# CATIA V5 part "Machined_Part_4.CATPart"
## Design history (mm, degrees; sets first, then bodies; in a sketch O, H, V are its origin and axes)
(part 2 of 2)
  Sketch80 on {plane type Tangent, Support face of Mirror1, RefPoint {point type OnSurface, Support face of Mirror1, RefPoint {point stored without definition}, Length 0, Direction (0, -166.6142, -986.0222)}}, origin (11500.5186, 164.9233, 4241.0796), H (0.9872, -0.1575, 0.0266), V (0, 0.1666, 0.986)
    point P1 (0, 0)
    intersected point E1 (0, 0) from Line67
    coincidence: E1 P1
  Hole76: placed by Sketch80, at (11500.5186, 164.9233, 4241.0796) direction (0.1598, 0.9734, -0.1645), diameter 7.7089, through (limit type 6)
  Sketch81 on {plane type Tangent, Support face of Mirror1, RefPoint {point type OnSurface, Support face of Mirror1, RefPoint {point stored without definition}, Length 0, Direction (0, -165.1506, -986.2684)}}, origin (11533.6115, 159.6283, 4241.9652), H (0.987, -0.1583, 0.0265), V (0, 0.1652, 0.9863)
    point P1 (0, 0)
    intersected point E1 (0, 0) from Line68
    coincidence: E1 P1
  Hole77: placed by Sketch81, at (11533.6115, 159.6283, 4241.9652) direction (0.1605, 0.9735, -0.163), diameter 7.7089, through (limit type 6)
  Sketch82 on {plane type Tangent, Support face of Mirror1, RefPoint {point type OnSurface, Support face of Mirror1, RefPoint {point stored without definition}, Length 0, Direction (0, -164.3356, -986.4045)}}, origin (11500.517, 173.296, 4291.0077), H (0.9868, -0.1598, 0.0266), V (0, 0.1643, 0.9864)
    point P1 (0, 0)
    intersected point E1 (0, 0) from Line69
    coincidence: E1 P1
  Hole78: placed by Sketch82, at (11500.517, 173.296, 4291.0077) direction (0.162, 0.9734, -0.1622), diameter 7.7089, through (limit type 6)
  Sketch83 on {plane type Tangent, Support face of Mirror1, RefPoint {point type OnSurface, Support face of Mirror1, RefPoint {point stored without definition}, Length 0, Direction (0, -162.7597, -986.6657)}}, origin (11533.5954, 167.9242, 4291.8914), H (0.9867, -0.1606, 0.0265), V (0, 0.1628, 0.9867)
    point P1 (0, 0)
    intersected point E1 (0, 0) from Line70
    coincidence: E1 P1
  Hole79: placed by Sketch83, at (11533.5954, 167.9242, 4291.8914) direction (0.1628, 0.9735, -0.1606), diameter 7.7089, through (limit type 6)
  Sketch84 on {plane type Tangent, Support face of Mirror1, RefPoint {point type OnSurface, Support face of Mirror1, RefPoint {point stored without definition}, Length 0, Direction (0, -161.7931, -986.8247)}}, origin (11533.5778, 176.1335, 4341.8382), H (0.9863, -0.1631, 0.0267), V (0, 0.1618, 0.9868)
    point P1 (0, 0)
    intersected point E1 (0, 0) from Line71
    coincidence: E1 P1
  Hole80: placed by Sketch84, at (11533.5778, 176.1335, 4341.8382) direction (0.1652, 0.9733, -0.1596), diameter 7.7089, through (limit type 6)
  Sketch85 on {plane type Tangent, Support face of Mirror1, RefPoint {point type OnSurface, Support face of Mirror1, RefPoint {point stored without definition}, Length 0, Direction (0, -164.041, -986.4535)}}, origin (11500.5075, 189.8922, 4390.8825), H (0.9859, -0.165, 0.0274), V (0, 0.164, 0.9865)
    point P1 (0, 0)
    intersected point E1 (0, 0) from Line73
    coincidence: E1 P1
  Hole81: placed by Sketch85, at (11500.5075, 189.8922, 4390.8825) direction (0.1672, 0.9726, -0.1617), diameter 7.7089, through (limit type 6)
  Sketch86 on {plane type Tangent, Support face of Mirror1, RefPoint {point type OnSurface, Support face of Mirror1, RefPoint {point stored without definition}, Length 0, Direction (0, -161.8829, -986.81)}}, origin (11533.5577, 184.3459, 4391.7892), H (0.9858, -0.1658, 0.0272), V (0, 0.1619, 0.9868)
    point P1 (0, 0)
    intersected point E1 (0, 0) from Line74
    coincidence: E1 P1
  Hole82: placed by Sketch86, at (11533.5577, 184.3459, 4391.7892) direction (0.168, 0.9728, -0.1596), diameter 7.7089, through (limit type 6)
  Sketch87 on {plane type Tangent, Support face of Mirror1, RefPoint {point type OnSurface, Support face of Mirror1, RefPoint {point stored without definition}, Length 0, Direction (0, -153.3155, -988.1773)}}, origin (11500.5026, 198.9361, 4447.1461), H (0.9853, -0.1687, 0.0262), V (0, 0.1533, 0.9882)
    point P1 (0, 0)
    intersected point E1 (0, 0) from Line75
    coincidence: E1 P1
  Hole83: placed by Sketch87, at (11500.5026, 198.9361, 4447.1461) direction (0.1707, 0.9737, -0.1511), diameter 7.7089, through (limit type 6)
  Sketch88 on {plane type Tangent, Support face of Mirror1, RefPoint {point type OnSurface, Support face of Mirror1, RefPoint {point stored without definition}, Length 0, Direction (0, -144.9294, -989.442)}}, origin (11500.4992, 205.5404, 4490.9343), H (0.9849, -0.1713, 0.0251), V (0, 0.1449, 0.9894)
    point P1 (0, 0)
    intersected point E1 (0, 0) from Line77
    coincidence: E1 P1
  Hole84: placed by Sketch88, at (11500.4992, 205.5404, 4490.9343) direction (0.1732, 0.9745, -0.1427), diameter 7.7089, through (limit type 6)
  Chamfer1: length 4.826, angle 45, on edge [face of Split4 | start face of Pocket1]
  Chamfer2: length 4.826, angle 45, on edge [face of Mirror1 | face of Mirror1]
  Fillet5: radius 3.175, on edge [start face of Pocket1 | face of Pocket1 from Sketch2.E2]; edge [start face of Pocket1 | face of Pocket1 from Sketch2.E1]; edge [face of Mirror1 | face of Mirror1] (x2)
  Sketch89 on face of Pad1, origin (11504.7787, 0, 3553.587), H (0.866, 0, 0.5), V (0, -1, 0)
    point P1 (0, 0)
    reference projected point E1 (0, 0) from Point8
    coincidence: E1 P1
  Hole85: placed by Sketch89, at (11504.7787, 0, 3553.587) direction (-0.5, 0, 0.866), diameter 6.3119, through (limit type 6)
  Sketch90 on face of Pad1, origin (11552.4023, 0, 3581.0825), H (0.866, 0, 0.5), V (0, -1, 0)
    point P1 (0, 0)
    reference projected point E1 (0, 0) from Point7
    coincidence: E1 P1
  Hole86: placed by Sketch90, at (11552.4023, 0, 3581.0825) direction (-0.5, 0, 0.866), diameter 6.3119, through (limit type 6)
